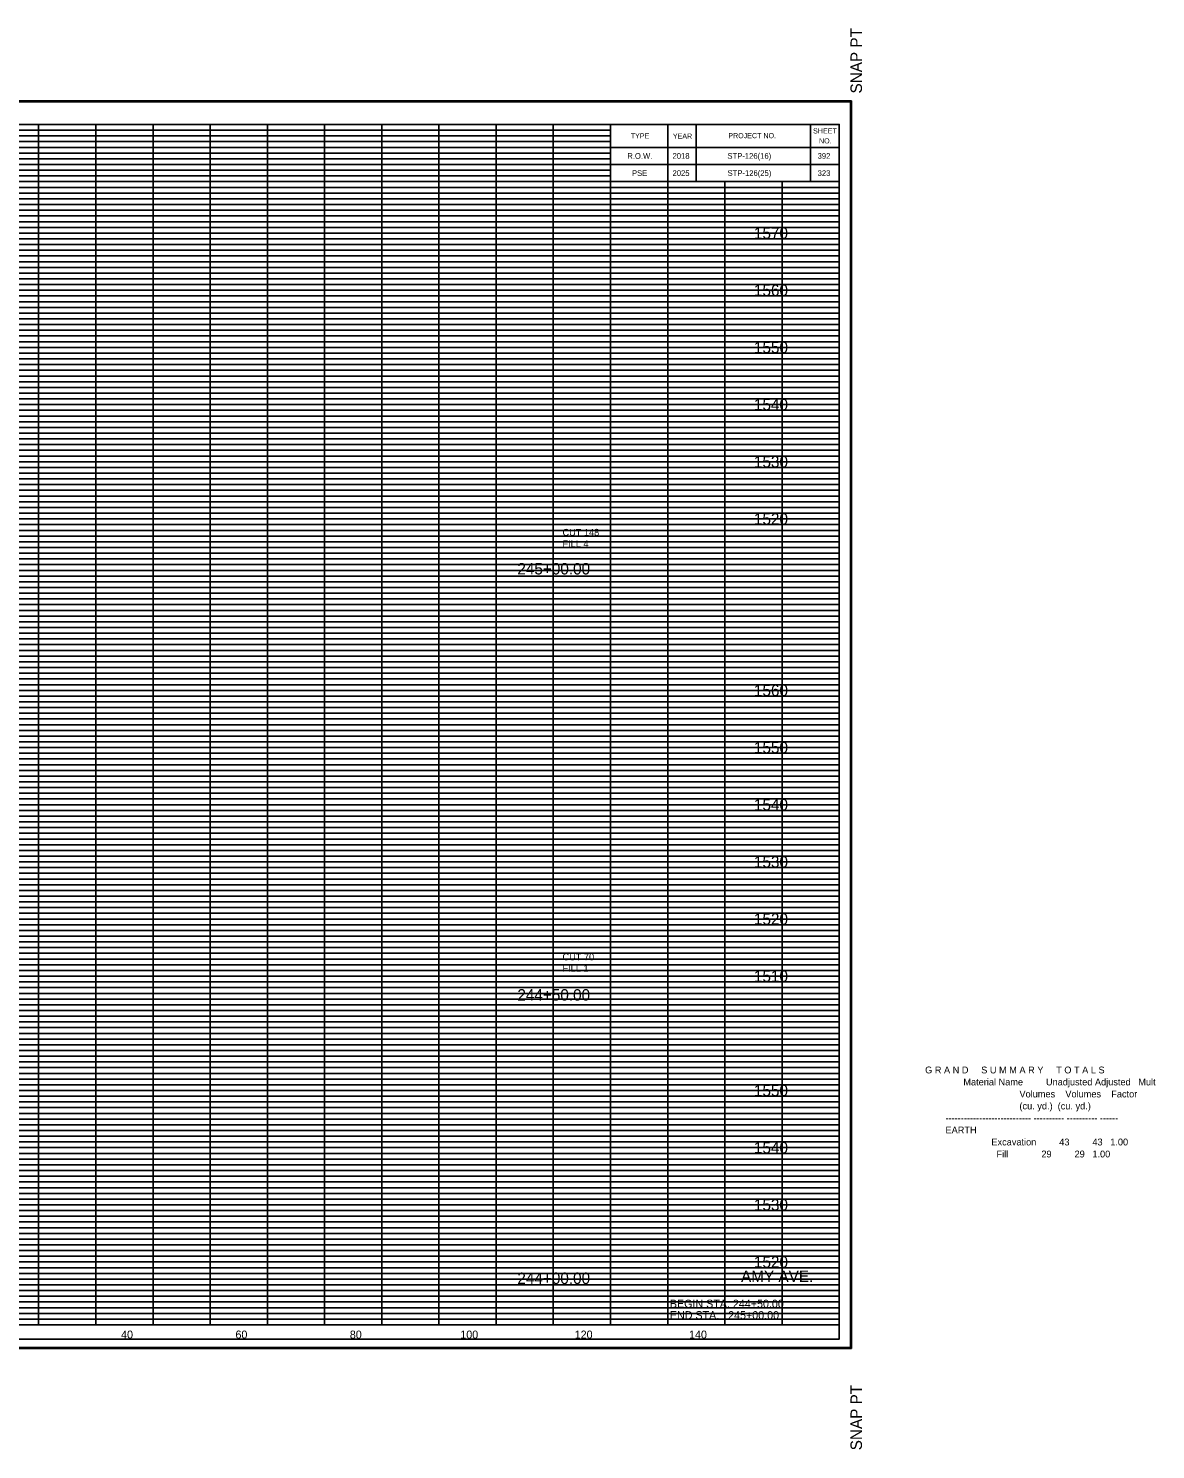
# Model space of a CAD drawing. Extents: x 955 to 1375, y 1248 to 3657.
# Drawn here: x 1178.2 to 1375.3, y 1248.2 to 1496.8 of the extents above; entities that cross this region are included whole.
import ezdxf

# ---------------------------------------------------------------- set-up
doc = ezdxf.new("R2010")
doc.units = 0
for name, color, linetype in [('DESIGN - SCRATCH - User 1', 7, 'Continuous'), ('DESIGN - SHEET - Corner Text', 7, 'Continuous'), ('DESIGN - SHEET - Light Grid', 7, 'Continuous'), ('DESIGN - SHEET - Linework', 7, 'Continuous'), ('DESIGN - SHEET - Plot Shape', 7, 'Continuous'), ('DESIGN - TYPICAL - Text', 7, 'Continuous'), ('DESIGN - UTILITIES - Cable (Overhead) with Text', 7, 'Continuous')]:
    doc.layers.add(name, color=color, linetype=linetype)

# ---------------------------------------------------------------- blocks, each defined once
blk = doc.blocks.new('XSTSHT')
at = {"layer": 'DESIGN - SCRATCH - User 1'}
for p, q in [((28.5, 20.45), (28.5, 20.45)), ((29.24, 20.45), (29.24, 20.45)), ((30.49, 20.45), (30.49, 20.45)), ((31.74, 20.45), (31.74, 20.45)), ((28.5, 20.15), (28.5, 20.15)), ((29.24, 20.15), (29.24, 20.15)), ((30.49, 20.15), (30.49, 20.15)), ((31.74, 20.15), (31.74, 20.15))]:
    blk.add_line(p, q, dxfattribs=at)
at = {"layer": 'DESIGN - SHEET - Light Grid'}
for p, q in [((16, 20.9), (24, 20.9)), ((24, 20.9), (28, 20.9)), ((16, 20.8), (24, 20.8)), ((16, 20.7), (24, 20.7)), ((24, 20.8), (28, 20.8)), ((24, 20.7), (28, 20.7)), ((16, 20.6), (24, 20.6)), ((16, 20.5), (24, 20.5)), ((16, 20.4), (24, 20.4)), ((24, 20.6), (28, 20.6)), ((24, 20.5), (28, 20.5)), ((24, 20.4), (28, 20.4)), ((16, 20.3), (24, 20.3)), ((16, 20.2), (24, 20.2)), ((24, 20.3), (28, 20.3)), ((24, 20.2), (28, 20.2)), ((16, 20.1), (24, 20.1)), ((16, 19.9), (24, 19.9)), ((24, 20.1), (28, 20.1)), ((24, 19.9), (32, 19.9)), ((16, 19.8), (24, 19.8)), ((16, 19.7), (24, 19.7)), ((24, 19.8), (32, 19.8)), ((24, 19.7), (32, 19.7)), ((16, 19.6), (24, 19.6)), ((16, 19.5), (24, 19.5)), ((16, 19.4), (24, 19.4)), ((24, 19.6), (32, 19.6)), ((24, 19.5), (32, 19.5)), ((24, 19.4), (32, 19.4)), ((16, 19.3), (24, 19.3)), ((16, 19.2), (24, 19.2)), ((24, 19.3), (32, 19.3)), ((24, 19.2), (32, 19.2)), ((16, 19.1), (24, 19.1)), ((16, 18.9), (24, 18.9)), ((24, 19.1), (32, 19.1)), ((24, 18.9), (32, 18.9)), ((16, 18.8), (24, 18.8)), ((16, 18.7), (24, 18.7)), ((24, 18.8), (32, 18.8)), ((24, 18.7), (32, 18.7)), ((16, 18.6), (24, 18.6)), ((16, 18.5), (24, 18.5)), ((16, 18.4), (24, 18.4)), ((24, 18.6), (32, 18.6)), ((24, 18.5), (32, 18.5)), ((24, 18.4), (32, 18.4)), ((16, 18.3), (24, 18.3)), ((16, 18.2), (24, 18.2)), ((24, 18.3), (32, 18.3)), ((24, 18.2), (32, 18.2)), ((16, 18.1), (24, 18.1)), ((24, 18.1), (32, 18.1)), ((16, 17.9), (24, 17.9)), ((16, 17.8), (24, 17.8)), ((16, 17.7), (24, 17.7)), ((24, 17.9), (32, 17.9)), ((24, 17.8), (32, 17.8)), ((24, 17.7), (32, 17.7)), ((16, 17.6), (24, 17.6)), ((16, 17.5), (24, 17.5)), ((24, 17.6), (32, 17.6)), ((24, 17.5), (32, 17.5)), ((16, 17.4), (24, 17.4)), ((16, 17.3), (24, 17.3)), ((16, 17.2), (24, 17.2)), ((24, 17.4), (32, 17.4)), ((24, 17.3), (32, 17.3)), ((24, 17.2), (32, 17.2)), ((16, 17.1), (24, 17.1)), ((24, 17.1), (32, 17.1)), ((16, 16.9), (24, 16.9)), ((16, 16.8), (24, 16.8)), ((16, 16.7), (24, 16.7)), ((24, 16.9), (32, 16.9)), ((24, 16.8), (32, 16.8)), ((24, 16.7), (32, 16.7)), ((16, 16.6), (24, 16.6)), ((16, 16.5), (24, 16.5)), ((24, 16.6), (32, 16.6)), ((24, 16.5), (32, 16.5)), ((16, 16.4), (24, 16.4)), ((16, 16.3), (24, 16.3)), ((16, 16.2), (24, 16.2)), ((24, 16.4), (32, 16.4)), ((24, 16.3), (32, 16.3)), ((24, 16.2), (32, 16.2)), ((16, 16.1), (24, 16.1)), ((24, 16.1), (32, 16.1)), ((16, 15.9), (24, 15.9)), ((16, 15.8), (24, 15.8)), ((16, 15.7), (24, 15.7)), ((24, 15.9), (32, 15.9)), ((24, 15.8), (32, 15.8)), ((24, 15.7), (32, 15.7)), ((16, 15.6), (24, 15.6)), ((16, 15.5), (24, 15.5)), ((24, 15.6), (32, 15.6)), ((24, 15.5), (32, 15.5)), ((16, 15.4), (24, 15.4)), ((16, 15.3), (24, 15.3)), ((16, 15.2), (24, 15.2)), ((24, 15.4), (32, 15.4)), ((24, 15.3), (32, 15.3)), ((24, 15.2), (32, 15.2)), ((16, 15.1), (24, 15.1)), ((24, 15.1), (32, 15.1)), ((16, 14.9), (24, 14.9)), ((16, 14.8), (24, 14.8)), ((16, 14.7), (24, 14.7)), ((24, 14.9), (32, 14.9)), ((24, 14.8), (32, 14.8)), ((24, 14.7), (32, 14.7)), ((16, 14.6), (24, 14.6)), ((16, 14.5), (24, 14.5)), ((24, 14.6), (32, 14.6)), ((24, 14.5), (32, 14.5)), ((16, 14.4), (24, 14.4)), ((16, 14.3), (24, 14.3)), ((16, 14.2), (24, 14.2)), ((24, 14.4), (32, 14.4)), ((24, 14.3), (32, 14.3)), ((24, 14.2), (32, 14.2)), ((16, 14.1), (24, 14.1)), ((24, 14.1), (32, 14.1)), ((16, 13.9), (24, 13.9)), ((16, 13.8), (24, 13.8)), ((16, 13.7), (24, 13.7)), ((24, 13.9), (32, 13.9)), ((24, 13.8), (32, 13.8)), ((24, 13.7), (32, 13.7)), ((16, 13.6), (24, 13.6)), ((16, 13.5), (24, 13.5)), ((24, 13.6), (32, 13.6)), ((24, 13.5), (32, 13.5)), ((16, 13.4), (24, 13.4)), ((16, 13.3), (24, 13.3)), ((16, 13.2), (24, 13.2)), ((24, 13.4), (32, 13.4)), ((24, 13.3), (32, 13.3)), ((24, 13.2), (32, 13.2)), ((16, 13.1), (24, 13.1)), ((24, 13.1), (32, 13.1)), ((16, 12.9), (24, 12.9)), ((16, 12.8), (24, 12.8)), ((16, 12.7), (24, 12.7)), ((24, 12.9), (32, 12.9)), ((24, 12.8), (32, 12.8)), ((24, 12.7), (32, 12.7)), ((16, 12.6), (24, 12.6)), ((16, 12.5), (24, 12.5)), ((24, 12.6), (32, 12.6)), ((24, 12.5), (32, 12.5)), ((16, 12.4), (24, 12.4)), ((16, 12.3), (24, 12.3)), ((16, 12.2), (24, 12.2)), ((24, 12.4), (32, 12.4)), ((24, 12.3), (32, 12.3)), ((24, 12.2), (32, 12.2)), ((16, 12.1), (24, 12.1)), ((24, 12.1), (32, 12.1)), ((16, 11.9), (24, 11.9)), ((16, 11.8), (24, 11.8)), ((16, 11.7), (24, 11.7)), ((24, 11.9), (32, 11.9)), ((24, 11.8), (32, 11.8)), ((24, 11.7), (32, 11.7)), ((16, 11.6), (24, 11.6)), ((16, 11.5), (24, 11.5)), ((24, 11.6), (32, 11.6)), ((24, 11.5), (32, 11.5)), ((16, 11.4), (24, 11.4)), ((16, 11.3), (24, 11.3)), ((16, 11.2), (24, 11.2)), ((24, 11.4), (32, 11.4)), ((24, 11.3), (32, 11.3)), ((24, 11.2), (32, 11.2)), ((16, 11.1), (24, 11.1)), ((24, 11.1), (32, 11.1)), ((16, 10.9), (24, 10.9)), ((16, 10.8), (24, 10.8)), ((16, 10.7), (24, 10.7)), ((24, 10.9), (32, 10.9)), ((24, 10.8), (32, 10.8)), ((24, 10.7), (32, 10.7)), ((16, 10.6), (24, 10.6)), ((16, 10.5), (24, 10.5)), ((24, 10.6), (32, 10.6)), ((24, 10.5), (32, 10.5)), ((16, 10.4), (24, 10.4)), ((16, 10.3), (24, 10.3)), ((16, 10.2), (24, 10.2)), ((24, 10.4), (32, 10.4)), ((24, 10.3), (32, 10.3)), ((24, 10.2), (32, 10.2)), ((16, 10.1), (24, 10.1)), ((24, 10.1), (32, 10.1)), ((16, 9.9), (24, 9.9)), ((16, 9.8), (24, 9.8)), ((16, 9.7), (24, 9.7)), ((24, 9.9), (32, 9.9)), ((24, 9.8), (32, 9.8)), ((24, 9.7), (32, 9.7)), ((16, 9.6), (24, 9.6)), ((16, 9.5), (24, 9.5)), ((24, 9.6), (32, 9.6)), ((24, 9.5), (32, 9.5)), ((16, 9.4), (24, 9.4)), ((16, 9.3), (24, 9.3)), ((16, 9.2), (24, 9.2)), ((24, 9.4), (32, 9.4)), ((24, 9.3), (32, 9.3)), ((24, 9.2), (32, 9.2)), ((16, 9.1), (24, 9.1)), ((24, 9.1), (32, 9.1)), ((16, 8.9), (24, 8.9)), ((16, 8.8), (24, 8.8)), ((24, 8.9), (32, 8.9)), ((24, 8.8), (32, 8.8)), ((16, 8.7), (24, 8.7)), ((16, 8.6), (24, 8.6)), ((16, 8.5), (24, 8.5)), ((24, 8.7), (32, 8.7)), ((24, 8.6), (32, 8.6)), ((24, 8.5), (32, 8.5)), ((16, 8.4), (24, 8.4)), ((16, 8.3), (24, 8.3)), ((24, 8.4), (32, 8.4)), ((24, 8.3), (32, 8.3)), ((16, 8.2), (24, 8.2)), ((16, 8.1), (24, 8.1)), ((24, 8.2), (32, 8.2)), ((24, 8.1), (32, 8.1)), ((16, 7.9), (24, 7.9)), ((16, 7.8), (24, 7.8)), ((24, 7.9), (32, 7.9)), ((24, 7.8), (32, 7.8)), ((16, 7.7), (24, 7.7)), ((16, 7.6), (24, 7.6)), ((16, 7.5), (24, 7.5)), ((24, 7.7), (32, 7.7)), ((24, 7.6), (32, 7.6)), ((24, 7.5), (32, 7.5)), ((16, 7.4), (24, 7.4)), ((16, 7.3), (24, 7.3)), ((24, 7.4), (32, 7.4)), ((24, 7.3), (32, 7.3)), ((16, 7.2), (24, 7.2)), ((16, 7.1), (24, 7.1)), ((24, 7.2), (32, 7.2)), ((24, 7.1), (32, 7.1)), ((16, 6.9), (24, 6.9)), ((16, 6.8), (24, 6.8)), ((24, 6.9), (32, 6.9)), ((24, 6.8), (32, 6.8)), ((16, 6.7), (24, 6.7)), ((16, 6.6), (24, 6.6)), ((16, 6.5), (24, 6.5)), ((24, 6.7), (32, 6.7)), ((24, 6.6), (32, 6.6)), ((24, 6.5), (32, 6.5)), ((16, 6.4), (24, 6.4)), ((16, 6.3), (24, 6.3)), ((24, 6.4), (32, 6.4)), ((24, 6.3), (32, 6.3)), ((16, 6.2), (24, 6.2)), ((16, 6.1), (24, 6.1)), ((24, 6.2), (32, 6.2)), ((24, 6.1), (32, 6.1)), ((16, 5.9), (24, 5.9)), ((16, 5.8), (24, 5.8)), ((24, 5.9), (32, 5.9)), ((24, 5.8), (32, 5.8)), ((16, 5.7), (24, 5.7)), ((16, 5.6), (24, 5.6)), ((16, 5.5), (24, 5.5)), ((24, 5.7), (32, 5.7)), ((24, 5.6), (32, 5.6)), ((24, 5.5), (32, 5.5)), ((16, 5.4), (24, 5.4)), ((16, 5.3), (24, 5.3)), ((24, 5.4), (32, 5.4)), ((24, 5.3), (32, 5.3)), ((16, 5.2), (24, 5.2)), ((16, 5.1), (24, 5.1)), ((24, 5.2), (32, 5.2)), ((24, 5.1), (32, 5.1)), ((16, 4.9), (24, 4.9)), ((16, 4.8), (24, 4.8)), ((24, 4.9), (32, 4.9)), ((24, 4.8), (32, 4.8)), ((16, 4.7), (24, 4.7)), ((16, 4.6), (24, 4.6)), ((16, 4.5), (24, 4.5)), ((24, 4.7), (32, 4.7)), ((24, 4.6), (32, 4.6)), ((24, 4.5), (32, 4.5)), ((16, 4.4), (24, 4.4)), ((16, 4.3), (24, 4.3)), ((24, 4.4), (32, 4.4)), ((24, 4.3), (32, 4.3)), ((16, 4.2), (24, 4.2)), ((16, 4.1), (24, 4.1)), ((24, 4.2), (32, 4.2)), ((24, 4.1), (32, 4.1)), ((16, 3.9), (24, 3.9)), ((16, 3.8), (24, 3.8)), ((24, 3.9), (32, 3.9)), ((24, 3.8), (32, 3.8)), ((16, 3.7), (24, 3.7)), ((16, 3.6), (24, 3.6)), ((16, 3.5), (24, 3.5)), ((24, 3.7), (32, 3.7)), ((24, 3.6), (32, 3.6)), ((24, 3.5), (32, 3.5)), ((16, 3.4), (24, 3.4)), ((16, 3.3), (24, 3.3)), ((24, 3.4), (32, 3.4)), ((24, 3.3), (32, 3.3)), ((16, 3.2), (24, 3.2)), ((16, 3.1), (24, 3.1)), ((24, 3.2), (32, 3.2)), ((24, 3.1), (32, 3.1)), ((16, 2.9), (24, 2.9)), ((16, 2.8), (24, 2.8)), ((24, 2.9), (32, 2.9)), ((24, 2.8), (32, 2.8)), ((16, 2.7), (24, 2.7)), ((16, 2.6), (24, 2.6)), ((16, 2.5), (24, 2.5)), ((24, 2.7), (32, 2.7)), ((24, 2.6), (32, 2.6)), ((24, 2.5), (32, 2.5)), ((16, 2.4), (24, 2.4)), ((16, 2.3), (24, 2.3)), ((24, 2.4), (32, 2.4)), ((24, 2.3), (32, 2.3)), ((16, 2.2), (24, 2.2)), ((16, 2.1), (24, 2.1)), ((24, 2.2), (32, 2.2)), ((24, 2.1), (32, 2.1)), ((16, 1.9), (24, 1.9)), ((16, 1.8), (24, 1.8)), ((24, 1.9), (32, 1.9)), ((24, 1.8), (32, 1.8)), ((16, 1.7), (24, 1.7)), ((16, 1.6), (24, 1.6)), ((16, 1.5), (24, 1.5)), ((24, 1.7), (32, 1.7)), ((24, 1.6), (32, 1.6)), ((24, 1.5), (32, 1.5)), ((16, 1.4), (24, 1.4)), ((16, 1.3), (24, 1.3)), ((24, 1.4), (32, 1.4)), ((24, 1.3), (32, 1.3)), ((16, 1.2), (24, 1.2)), ((16, 1.1), (24, 1.1)), ((24, 1.2), (32, 1.2)), ((24, 1.1), (32, 1.1)), ((16, 0.9), (24, 0.9)), ((16, 0.8), (24, 0.8)), ((24, 0.9), (32, 0.9)), ((24, 0.8), (32, 0.8)), ((16, 0.7), (24, 0.7)), ((16, 0.6), (24, 0.6)), ((16, 0.5), (24, 0.5)), ((24, 0.7), (32, 0.7)), ((24, 0.6), (32, 0.6)), ((24, 0.5), (32, 0.5)), ((16, 0.4), (24, 0.4)), ((16, 0.3), (24, 0.3)), ((24, 0.4), (32, 0.4)), ((24, 0.3), (32, 0.3)), ((16, 0.2), (24, 0.2)), ((16, 0.1), (24, 0.1)), ((24, 0.2), (32, 0.2)), ((24, 0.1), (32, 0.1))]:
    blk.add_line(p, q, dxfattribs=at)
at = {"layer": 'DESIGN - SHEET - Linework'}
for p, q in [((-1.823, 21.414), (32.217, 21.414)), ((32.217, 21.414), (32.217, -0.414)), ((18, 0), (18, 21)), ((19, 0), (19, 21)), ((20, 0), (20, 21)), ((21, 0), (21, 21)), ((22, 0), (22, 21)), ((23, 0), (23, 21)), ((24, 0), (24, 21)), ((25, 0), (25, 21)), ((26, 0), (26, 21)), ((27, 0), (27, 21)), ((0, 20), (28, 20)), ((28, 0), (28, 20)), ((29, 0), (29, 20)), ((30, 0), (30, 20)), ((31, 0), (31, 20)), ((0, 19), (32, 19)), ((0, 18), (32, 18)), ((0, 17), (32, 17)), ((0, 16), (32, 16)), ((0, 15), (32, 15)), ((0, 14), (32, 14)), ((0, 13), (32, 13)), ((0, 12), (32, 12)), ((0, 11), (32, 11)), ((0, 10), (32, 10)), ((0, 9), (32, 9)), ((0, 8), (32, 8)), ((0, 7), (32, 7)), ((0, 6), (32, 6)), ((0, 5), (32, 5)), ((0, 4), (32, 4)), ((0, 3), (32, 3)), ((0, 2), (32, 2)), ((0, 1), (32, 1)), ((-1.823, -0.414), (32.217, -0.414))]:
    blk.add_line(p, q, dxfattribs=at)
for points in [[(0, 21), (0, 0), (32, 0), (32, 21), (0, 21)], [(28, 21), (28, 20), (32, 20), (32, 21), (31.5, 21), (31.5, 20), (29.5, 20), (29.5, 21), (29, 21), (29, 20), (32, 20), (28, 20), (28, 20.3), (32, 20.3), (32, 20.6), (28, 20.6)]]:
    blk.add_lwpolyline(points, dxfattribs=at)
at = {"layer": 'DESIGN - SHEET - Plot Shape'}
for points in [[(-1.803, 21.394), (32.197, 21.394), (32.197, -0.394), (-1.803, -0.394)], [(-0.85, 21), (32, 21), (32, -0.25), (-0.85, -0.25)]]:
    blk.add_lwpolyline(points, close=True, dxfattribs=at)
at = {"layer": 'DESIGN - SHEET - Corner Text'}
for s, p in [('  SNAP PT', (32.397, 21.394)), ('SNAP PT  ', (32.397, -2.194))]:
    blk.add_text(s, height=0.2, rotation=90, dxfattribs=at).set_placement(p)
for s, p in [('SHEET', (31.543, 20.843)), ('TYPE', (28.354, 20.756)), ('YEAR', (29.09, 20.752)), ('PROJECT NO.', (30.06, 20.76)), ('NO.', (31.646, 20.669))]:
    blk.add_text(s, height=0.09, dxfattribs=at).set_placement(p)

msp = doc.modelspace()

# ---------------------------------------------------------------- linework, layer by layer
at = {"layer": 'DESIGN - SHEET - Plot Shape'}
msp.add_lwpolyline([(991.5, 1267.5), (1320, 1267.5), (1320, 1480), (991.5, 1480)], close=True, dxfattribs=at)

# ---------------------------------------------------------------- block references
at = {"layer": 'DESIGN - UTILITIES - Cable (Overhead) with Text', "xscale": 10, "yscale": 10}
msp.add_blockref('XSTSHT', (1000, 1270), dxfattribs=at)

# ---------------------------------------------------------------- texts
at = {"layer": 'DESIGN - SHEET - Corner Text'}
for s, height, p in [('R.O.W.', 1, (1282.94, 1474)), ('2018', 1, (1290.85, 1474)), ('STP-126(16)', 1, (1300.45, 1474)), ('392', 1, (1316.22, 1474)), ('PSE', 1, (1283.75, 1471)), ('2025', 1, (1290.85, 1471)), ('STP-126(25)', 1, (1300.47, 1471)), ('323', 1, (1316.22, 1471)), ('AMY AVE.', 2, (1302.83, 1277.5)), ('BEGIN STA. 244+50.00', 1.4, (1290.38, 1273)), ('END STA.   245+00.00', 1.4, (1290.38, 1271))]:
    msp.add_text(s, height=height, dxfattribs=at).set_placement(p)
at = {"layer": 'DESIGN - TYPICAL - Text'}
for s, height, p in [('     1570     ', 2, (1301.37, 1460)), ('     1560     ', 2, (1301.37, 1450)), ('     1550     ', 2, (1301.37, 1440)), ('     1540     ', 2, (1301.37, 1430)), ('     1530     ', 2, (1301.37, 1420)), ('     1520     ', 2, (1301.37, 1410)), ('CUT 148', 1.2, (1271.61, 1408.05)), ('FILL 4', 1.2, (1271.61, 1406.05)), ('     245+00.00     ', 2, (1260, 1401.28)), ('     1560     ', 2, (1301.37, 1380)), ('     1550     ', 2, (1301.37, 1370)), ('     1540     ', 2, (1301.37, 1360)), ('     1530     ', 2, (1301.37, 1350)), ('     1520     ', 2, (1301.37, 1340)), ('CUT 70', 1.2, (1271.61, 1333.78)), ('FILL 1', 1.2, (1271.61, 1331.78)), ('     1510     ', 2, (1301.37, 1330)), ('     244+50.00     ', 2, (1260, 1326.73)), ('G R A N D     S U M M A R Y     T O T A L S', 1.2, (1335.02, 1313.99)), ('               Material Name         Unadjusted Adjusted   Mult', 1.2, (1335.02, 1311.89)), ('     1550     ', 2, (1301.37, 1310)), ('                                     Volumes    Volumes    Factor', 1.2, (1335.02, 1309.79)), ('                                     (cu. yd.)  (cu. yd.)', 1.2, (1335.02, 1307.69)), ('        ---------------------------- ---------- ---------- ------', 1.2, (1335.02, 1305.59)), ('        EARTH', 1.2, (1335.02, 1303.49)), ('     1540     ', 2, (1301.37, 1300)), ('                          Excavation         43         43   1.00', 1.2, (1335.02, 1301.39)), ('                            Fill             29         29   1.00', 1.2, (1335.02, 1299.29)), ('     1530     ', 2, (1301.37, 1290)), ('     1520     ', 2, (1301.37, 1280)), ('     244+00.00     ', 2, (1260, 1277.15)), ('     40     ', 1.4, (1191.82, 1267.6)), ('     60     ', 1.4, (1211.82, 1267.6)), ('     80     ', 1.4, (1231.82, 1267.6)), ('     100     ', 1.4, (1251.14, 1267.6)), ('     120     ', 1.4, (1271.14, 1267.6)), ('     140     ', 1.4, (1291.14, 1267.6))]:
    msp.add_text(s, height=height, dxfattribs=at).set_placement(p)

doc.saveas('drawing.dxf')
